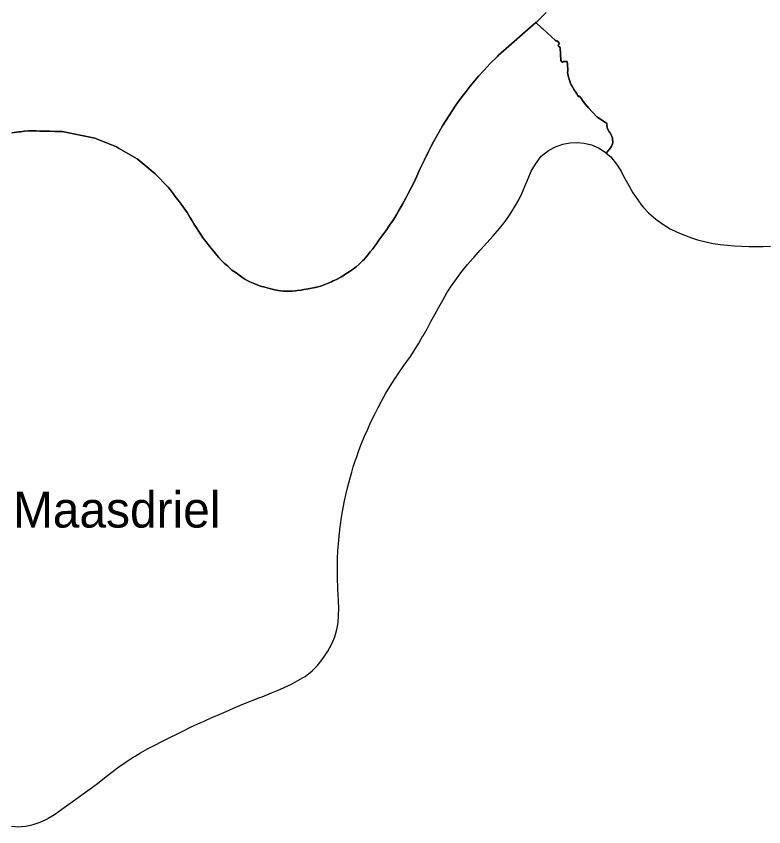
# Model space of a CAD drawing. Extents: x 113371 to 291721, y 393993 to 520143.
# Drawn here: x 148639 to 159083, y 416466 to 427782 of the extents above; entities that cross this region are included whole.
import ezdxf

# ---------------------------------------------------------------- set-up
doc = ezdxf.new("R2010")
doc.units = 0
doc.layers.add('Default', color=7, linetype='Continuous')
doc.layers.add('plaatsnamen', color=7, linetype='Continuous')

msp = doc.modelspace()

# ---------------------------------------------------------------- linework, layer by layer
at = {"layer": 'Default'}
for points in [[(153986.505625, 425071.1725), (154034.975625, 425158.1925), (154087.115625, 425250.9725), (154120.345625, 425313.7825), (154161.605625, 425394.4425), (154201.585625, 425476.5625), (154249.765625, 425580.5525), (154278.395625, 425644.2125), (154341.195625, 425778.3425), (154397.125625, 425894.2625), (154430.575625, 425960.3225), (154468.725625, 426028.9725), (154595.535625, 426249.2025), (154780.515625, 426538.5825), (154849.085625, 426638.0225), (154887.425625, 426683.3225), (154923.725625, 426732.1225), (154978.845625, 426803.2425), (155026.375625, 426861.5125), (155098.405625, 426944.2925), (155176.415625, 427030.0625), (155260.355625, 427121.3925), (155361.635625, 427221.1325), (155376.935625, 427238.0325), (155407.135625, 427265.8925), (155899.955625, 427692.0425), (155902.265625, 427694.0425), (155931.275625, 427722.2525), (156042.365625, 427833.5825)], [(156042.365625, 427833.5825), (155931.275625, 427722.2525), (155902.265625, 427694.0425), (155899.955625, 427692.0425), (155909.255625, 427683.7325), (155968.405625, 427628.1825), (155979.005625, 427618.3525), (155983.445625, 427615.4525), (155987.855625, 427611.0025), (155989.615625, 427609.2325), (156171.875625, 427441.2025), (156174.015625, 427439.5625), (156174.105625, 427439.5525), (156195.345625, 427435.7825)], [(156201.355625, 427434.5425), (156200.165625, 427434.7925), (156195.345625, 427435.7825), (156174.105625, 427439.5525), (156174.015625, 427439.5625), (156171.875625, 427441.2025), (155989.615625, 427609.2325), (155987.855625, 427611.0025), (155983.445625, 427615.4525), (155979.005625, 427618.3525), (155968.405625, 427628.1825), (155909.255625, 427683.7325), (155899.955625, 427692.0425), (155407.135625, 427265.8925), (155376.935625, 427238.0325), (155361.635625, 427221.1325), (155260.355625, 427121.3925), (155176.415625, 427030.0625), (155098.405625, 426944.2925), (155026.375625, 426861.5125), (154978.845625, 426803.2425), (154923.725625, 426732.1225), (154887.425625, 426683.3225), (154849.085625, 426638.0225), (154780.515625, 426538.5825), (154595.535625, 426249.2025), (154468.725625, 426028.9725), (154430.575625, 425960.3225), (154397.125625, 425894.2625), (154341.195625, 425778.3425), (154278.395625, 425644.2125), (154249.765625, 425580.5525), (154201.585625, 425476.5625), (154161.605625, 425394.4425), (154120.345625, 425313.7825), (154087.115625, 425250.9725), (154034.975625, 425158.1925), (153986.505625, 425071.1725)], [(156195.345625, 427435.7825), (156200.165625, 427434.7925), (156201.355625, 427434.5425), (156227.355625, 427400.2725), (156223.255625, 427395.3825), (156222.145625, 427393.2125), (156211.015625, 427377.6825), (156216.185625, 427365.5225), (156218.345625, 427363.6225), (156224.265625, 427357.8325), (156235.055625, 427345.2225), (156235.225625, 427345.0325), (156235.945625, 427344.1925), (156237.925625, 427341.0425), (156238.325625, 427340.4225), (156240.565625, 427336.8625), (156239.085625, 427329.9925), (156239.865625, 427309.1825), (156239.915625, 427307.6425), (156240.125625, 427301.9925), (156240.705625, 427287.4625), (156240.705625, 427287.3325), (156240.735625, 427286.8525), (156242.135625, 427259.3225), (156242.145625, 427259.1825), (156244.425625, 427214.5825), (156245.195625, 427199.6225), (156246.965625, 427165.0925), (156260.145625, 427143.7625), (156259.175625, 427141.0625), (156264.055625, 427141.4025), (156277.055625, 427142.3125), (156278.595625, 427142.4225), (156280.065625, 427142.5225), (156281.015625, 427146.8325), (156282.795625, 427147.9825), (156283.095625, 427148.1825), (156285.415625, 427148.2525)], [(156318.305625, 427150.8125), (156317.945625, 427149.3425), (156285.415625, 427148.2525), (156283.095625, 427148.1825), (156282.795625, 427147.9825), (156281.015625, 427146.8325), (156280.065625, 427142.5225), (156278.595625, 427142.4225), (156277.055625, 427142.3125), (156264.055625, 427141.4025), (156259.175625, 427141.0625), (156260.145625, 427143.7625), (156246.965625, 427165.0925), (156245.195625, 427199.6225), (156244.425625, 427214.5825), (156242.145625, 427259.1825), (156242.135625, 427259.3225), (156240.735625, 427286.8525), (156240.705625, 427287.3325), (156240.705625, 427287.4625), (156240.125625, 427301.9925), (156239.915625, 427307.6425), (156239.865625, 427309.1825), (156239.085625, 427329.9925), (156240.565625, 427336.8625), (156238.325625, 427340.4225), (156237.925625, 427341.0425), (156235.945625, 427344.1925), (156235.225625, 427345.0325), (156235.055625, 427345.2225), (156224.265625, 427357.8325), (156218.345625, 427363.6225), (156216.185625, 427365.5225), (156211.015625, 427377.6825), (156222.145625, 427393.2125), (156223.255625, 427395.3825), (156227.355625, 427400.2725), (156201.355625, 427434.5425)], [(156285.415625, 427148.2525), (156317.945625, 427149.3425), (156318.305625, 427150.8125), (156336.875625, 427151.6425), (156337.755625, 427134.0525), (156338.455625, 427120.0425), (156338.465625, 427119.8425), (156338.525625, 427118.4925), (156343.385625, 427018.6225), (156341.935625, 426994.3425), (156341.985625, 426993.3625), (156342.115625, 426990.5325), (156343.105625, 426983.7925), (156343.625625, 426980.2325), (156349.825625, 426950.9425), (156359.485625, 426919.0025), (156361.965625, 426908.6725), (156365.725625, 426892.7525), (156367.265625, 426888.2325), (156376.835625, 426861.0325), (156377.065625, 426860.3825), (156377.795625, 426858.3425), (156393.625625, 426822.7225), (156408.625625, 426797.8225), (156415.205625, 426786.7225), (156417.835625, 426782.2825), (156419.145625, 426780.0525), (156425.385625, 426769.4325), (156425.855625, 426768.6025), (156430.375625, 426760.7725), (156430.785625, 426760.0525), (156441.945625, 426742.2325), (156455.235625, 426721.2825), (156455.575625, 426720.7225), (156469.015625, 426699.3125), (156473.825625, 426691.5525), (156474.775625, 426690.0025), (156481.415625, 426679.6625)], [(156494.665625, 426660.7725), (156483.685625, 426676.1125), (156481.415625, 426679.6625), (156474.775625, 426690.0025), (156473.825625, 426691.5525), (156469.015625, 426699.3125), (156455.575625, 426720.7225), (156455.235625, 426721.2825), (156441.945625, 426742.2325), (156430.785625, 426760.0525), (156430.375625, 426760.7725), (156425.855625, 426768.6025), (156425.385625, 426769.4325), (156419.145625, 426780.0525), (156417.835625, 426782.2825), (156415.205625, 426786.7225), (156408.625625, 426797.8225), (156393.625625, 426822.7225), (156377.795625, 426858.3425), (156377.065625, 426860.3825), (156376.835625, 426861.0325), (156367.265625, 426888.2325), (156365.725625, 426892.7525), (156361.965625, 426908.6725), (156359.485625, 426919.0025), (156349.825625, 426950.9425), (156343.625625, 426980.2325), (156343.105625, 426983.7925), (156342.115625, 426990.5325), (156341.985625, 426993.3625), (156341.935625, 426994.3425), (156343.385625, 427018.6225), (156338.525625, 427118.4925), (156338.465625, 427119.8425), (156338.455625, 427120.0425), (156337.755625, 427134.0525), (156336.875625, 427151.6425), (156318.305625, 427150.8125)], [(156481.415625, 426679.6625), (156483.685625, 426676.1125), (156494.665625, 426660.7725), (156498.025625, 426662.7325), (156506.235625, 426667.5125), (156534.795625, 426629.1025), (156561.575625, 426593.1625), (156561.675625, 426593.0325), (156613.225625, 426523.4425), (156615.765625, 426524.8725), (156616.735625, 426523.8025), (156636.105625, 426502.4125), (156752.645625, 426378.5925), (156752.735625, 426378.5225), (156753.415625, 426378.0425), (156761.775625, 426373.8725), (156891.725625, 426285.9125), (156888.245625, 426277.0525), (156888.435625, 426272.2725), (156890.175625, 426257.5925), (156890.785625, 426250.3125), (156892.625625, 426235.5425), (156893.705625, 426230.4125), (156898.835625, 426217.3025), (156900.565625, 426212.0525), (156908.355625, 426192.9925), (156914.825625, 426180.1325), (156920.655625, 426171.3825), (156931.315625, 426157.1525), (156936.125625, 426149.4225), (156940.435625, 426143.2825), (156943.795625, 426137.9625), (156948.305625, 426129.1925), (156950.325625, 426125.1725), (156954.465625, 426115.7425), (156959.705625, 426102.4525), (156963.565625, 426092.9225), (156968.285625, 426077.2225)], [(156975.075625, 426021.4225), (156969.925625, 426066.0525), (156968.285625, 426077.2225), (156963.565625, 426092.9225), (156959.705625, 426102.4525), (156954.465625, 426115.7425), (156950.325625, 426125.1725), (156948.305625, 426129.1925), (156943.795625, 426137.9625), (156940.435625, 426143.2825), (156936.125625, 426149.4225), (156931.315625, 426157.1525), (156920.655625, 426171.3825), (156914.825625, 426180.1325), (156908.355625, 426192.9925), (156900.565625, 426212.0525), (156898.835625, 426217.3025), (156893.705625, 426230.4125), (156892.625625, 426235.5425), (156890.785625, 426250.3125), (156890.175625, 426257.5925), (156888.435625, 426272.2725), (156888.245625, 426277.0525), (156891.725625, 426285.9125), (156761.775625, 426373.8725), (156753.415625, 426378.0425), (156752.735625, 426378.5225), (156752.645625, 426378.5925), (156636.105625, 426502.4125), (156616.735625, 426523.8025), (156615.765625, 426524.8725), (156613.225625, 426523.4425), (156561.675625, 426593.0325), (156561.575625, 426593.1625), (156534.795625, 426629.1025), (156506.235625, 426667.5125), (156498.025625, 426662.7325), (156494.665625, 426660.7725)], [(148575.925625, 426153.8125), (148676.105625, 426166.0625), (148700.015625, 426168.9225), (148754.025625, 426175.3925), (148813.925625, 426182.4925), (148853.355625, 426181.3425), (148917.635625, 426179.9725), (148971.455625, 426178.8325), (149021.535625, 426177.5425), (149081.715625, 426176.1125), (149112.835625, 426175.2325), (149185.675625, 426173.4925), (149253.215625, 426171.9225), (149279.585625, 426171.4925), (149739.275625, 426079.8825), (150038.015625, 425958.2325), (150068.685625, 425940.6425), (150327.555625, 425792.1125), (150434.675625, 425702.7025), (150581.285625, 425580.5025), (150761.515625, 425396.2825), (150788.465625, 425361.9225), (150831.815625, 425306.2925), (150861.375625, 425266.7025), (150898.585625, 425220.4025), (150921.355625, 425188.2725), (150966.075625, 425126.1625), (151003.985625, 425073.4425), (151028.195625, 425039.9025), (151066.175625, 424975.8425), (151097.375625, 424923.7125), (151120.775625, 424884.9225), (151134.415625, 424862.0725)], [(148676.105625, 426166.0625), (148575.925625, 426153.8125)], [(151348.775625, 424559.5025), (151292.245625, 424632.0425), (151247.675625, 424689.2025), (151218.805625, 424733.3325), (151190.445625, 424776.6025), (151156.045625, 424828.3525), (151134.415625, 424862.0725), (151120.775625, 424884.9225), (151097.375625, 424923.7125), (151066.175625, 424975.8425), (151028.195625, 425039.9025), (151003.985625, 425073.4425), (150966.075625, 425126.1625), (150921.355625, 425188.2725), (150898.585625, 425220.4025), (150861.375625, 425266.7025), (150831.815625, 425306.2925), (150788.465625, 425361.9225), (150761.515625, 425396.2825), (150581.285625, 425580.5025), (150434.675625, 425702.7025), (150327.555625, 425792.1125), (150068.685625, 425940.6425), (150038.015625, 425958.2325), (149739.275625, 426079.8825), (149279.585625, 426171.4925), (149253.215625, 426171.9225), (149185.675625, 426173.4925), (149112.835625, 426175.2325), (149081.715625, 426176.1125), (149021.535625, 426177.5425), (148971.455625, 426178.8325), (148917.635625, 426179.9725), (148853.355625, 426181.3425), (148813.925625, 426182.4925), (148754.025625, 426175.3925), (148700.015625, 426168.9225), (148676.105625, 426166.0625)], [(156968.285625, 426077.2225), (156969.925625, 426066.0525), (156975.075625, 426021.4225), (156973.295625, 426012.8925), (156971.115625, 426002.4525), (156954.615625, 425966.7825), (156941.825625, 425942.0225), (156928.745625, 425926.5925), (156882.925625, 425871.2325), (156944.285625, 425817.7525), (157025.285625, 425717.7525), (157089.285625, 425617.7525), (157106.235625, 425586.3825), (157143.285625, 425517.7525), (157179.295625, 425451.0825), (157197.285625, 425417.7525), (157255.285625, 425317.7525), (157321.285625, 425217.7525), (157374.285625, 425143.7525), (157403.605625, 425112.0925), (157474.285625, 425035.7525), (157574.285625, 424948.7525), (157674.285625, 424876.7525), (157774.285625, 424815.7525), (157874.285625, 424767.7525), (157974.195625, 424724.9425), (158074.285625, 424685.7525), (158154.785625, 424659.9925), (158174.285625, 424653.7525), (158274.285625, 424629.7525), (158374.285625, 424610.7525), (158374.485625, 424610.7325), (158408.045625, 424606.0325), (158474.285625, 424596.7525), (158574.285625, 424583.7525), (158674.285625, 424575.7525), (158774.285625, 424569.7525), (158874.285625, 424566.7525)], [(154864.285625, 424217.7525), (154944.285625, 424317.7525), (155019.695625, 424400.6225), (155035.285625, 424417.7525), (155122.335625, 424517.7225), (155124.035625, 424519.6825), (155213.285625, 424617.7525), (155304.285625, 424717.7525), (155390.285625, 424817.7525), (155471.285625, 424917.7525), (155539.285625, 425017.7525), (155599.965625, 425114.0625), (155602.285625, 425117.7525), (155659.285625, 425217.7525), (155705.285625, 425317.7525), (155748.285625, 425417.7525), (155781.095625, 425492.3025), (155792.285625, 425517.7525), (155835.285625, 425617.7525), (155891.285625, 425717.7525), (155974.285625, 425826.7525), (156074.285625, 425906.7525), (156174.285625, 425959.7525), (156274.285625, 425996.7525), (156374.285625, 426015.7525), (156474.285625, 426019.7525), (156574.285625, 426010.7525), (156674.285625, 425985.7525), (156774.285625, 425944.7525), (156852.665625, 425893.0325), (156874.285625, 425878.7525), (156882.925625, 425871.2325), (156928.745625, 425926.5925), (156941.825625, 425942.0225), (156954.615625, 425966.7825), (156971.115625, 426002.4525), (156973.295625, 426012.8925), (156975.075625, 426021.4225)], [(153986.505625, 425071.1725), (153954.985625, 425018.4225), (153899.815625, 424924.7625), (153865.435625, 424876.3625), (153815.405625, 424803.1825), (153746.665625, 424709.1125), (153720.755625, 424673.5925), (153706.655625, 424653.2325), (153662.615625, 424592.2225), (153654.105625, 424581.0325), (153633.125625, 424551.2725), (153621.515625, 424536.0025), (153585.415625, 424490.7325), (153542.765625, 424438.5725), (153512.715625, 424403.4925), (153498.005625, 424387.3125), (153480.595625, 424369.4825), (153453.115625, 424343.3825), (153429.105625, 424321.2925), (153387.325625, 424284.2525), (153349.625625, 424255.6325), (153324.895625, 424237.6325), (153276.455625, 424203.7625), (153266.005625, 424196.9925), (153203.995625, 424156.7925), (153173.755625, 424138.8925), (153112.995625, 424107.3325), (153068.065625, 424085.4725), (153045.805625, 424075.3425), (153019.435625, 424064.0125), (152972.395625, 424044.4625), (152927.335625, 424026.6425), (152904.085625, 424018.4925), (152891.335625, 424014.5725), (152855.995625, 424004.9025), (152792.835625, 423990.2525), (152742.195625, 423980.3625), (152719.815625, 423976.2325)], [(152719.815625, 423976.2325), (152742.195625, 423980.3625), (152792.835625, 423990.2525), (152855.995625, 424004.9025), (152891.335625, 424014.5725), (152904.085625, 424018.4925), (152927.335625, 424026.6425), (152972.395625, 424044.4625), (153019.435625, 424064.0125), (153045.805625, 424075.3425), (153068.065625, 424085.4725), (153112.995625, 424107.3325), (153173.755625, 424138.8925), (153203.995625, 424156.7925), (153266.005625, 424196.9925), (153276.455625, 424203.7625), (153324.895625, 424237.6325), (153349.625625, 424255.6325), (153387.325625, 424284.2525), (153429.105625, 424321.2925), (153453.115625, 424343.3825), (153480.595625, 424369.4825), (153498.005625, 424387.3125), (153512.715625, 424403.4925), (153542.765625, 424438.5725), (153585.415625, 424490.7325), (153621.515625, 424536.0025), (153633.125625, 424551.2725), (153654.105625, 424581.0325), (153662.615625, 424592.2225), (153706.655625, 424653.2325), (153720.755625, 424673.5925), (153746.665625, 424709.1125), (153815.405625, 424803.1825), (153865.435625, 424876.3625), (153899.815625, 424924.7625), (153954.985625, 425018.4225), (153986.505625, 425071.1725)], [(151134.415625, 424862.0725), (151156.045625, 424828.3525), (151190.445625, 424776.6025), (151218.805625, 424733.3325), (151247.675625, 424689.2025), (151292.245625, 424632.0425), (151348.775625, 424559.5025), (151348.955625, 424559.2925), (151357.975625, 424547.7125), (151380.285625, 424519.6525), (151466.485625, 424419.1525), (151511.135625, 424367.1025), (151546.265625, 424335.0325), (151589.815625, 424294.8725), (151652.085625, 424236.9525), (151713.725625, 424197.1925), (151769.385625, 424158.3325), (151804.495625, 424129.8825), (151832.035625, 424112.0925), (151872.945625, 424089.4925), (151902.545625, 424074.4625), (151925.715625, 424063.3825), (151948.565625, 424053.2125), (151972.355625, 424043.7225), (152006.455625, 424030.9325), (152038.375625, 424019.8025), (152053.355625, 424015.2525), (152112.955625, 423997.4025), (152144.235625, 423989.0025), (152176.835625, 423980.8325), (152252.035625, 423963.6825), (152254.015625, 423961.5225), (152300.095625, 423954.4825), (152331.645625, 423949.2625), (152366.655625, 423945.3925), (152379.665625, 423944.5125), (152436.585625, 423943.7225), (152496.305625, 423945.1425)], [(152719.815625, 423976.2325), (152689.965625, 423970.7325), (152658.675625, 423965.9825), (152618.345625, 423958.9225), (152563.625625, 423950.6325), (152541.915625, 423948.1325), (152496.305625, 423945.1425), (152436.585625, 423943.7225), (152379.665625, 423944.5125), (152366.655625, 423945.3925), (152331.645625, 423949.2625), (152300.095625, 423954.4825), (152254.015625, 423961.5225), (152252.035625, 423963.6825), (152176.835625, 423980.8325), (152144.235625, 423989.0025), (152112.955625, 423997.4025), (152053.355625, 424015.2525), (152038.375625, 424019.8025), (152006.455625, 424030.9325), (151972.355625, 424043.7225), (151948.565625, 424053.2125), (151925.715625, 424063.3825), (151902.545625, 424074.4625), (151872.945625, 424089.4925), (151832.035625, 424112.0925), (151804.495625, 424129.8825), (151769.385625, 424158.3325), (151713.725625, 424197.1925), (151652.085625, 424236.9525), (151589.815625, 424294.8725), (151546.265625, 424335.0325), (151511.135625, 424367.1025), (151466.485625, 424419.1525), (151380.285625, 424519.6525), (151357.975625, 424547.7125), (151348.955625, 424559.2925), (151348.775625, 424559.5025)], [(158874.285625, 424566.7525), (158973.985625, 424564.7625), (158974.285625, 424564.7525), (159074.285625, 424567.7525), (159174.285625, 424571.7525)], [(153272.285625, 421217.7525), (153300.285625, 421317.7525), (153327.285625, 421417.7525), (153348.625625, 421488.8825), (153357.285625, 421517.7525), (153390.055625, 421614.1225), (153391.285625, 421617.7525), (153427.285625, 421717.7525), (153464.285625, 421817.7525), (153505.285625, 421917.7525), (153549.285625, 422017.7525), (153593.285625, 422117.7525), (153643.285625, 422217.7525), (153694.285625, 422317.7525), (153737.035625, 422399.9725), (153746.285625, 422417.7525), (153804.285625, 422517.7525), (153863.285625, 422617.7525), (153926.285625, 422717.7525), (153951.195625, 422753.9525), (153955.185625, 422759.7525), (153995.285625, 422817.7525), (154026.845625, 422862.8425), (154065.285625, 422917.7525), (154136.285625, 423017.7525), (154202.285625, 423117.7525), (154262.285625, 423217.7525), (154321.285625, 423317.7525), (154322.585625, 423320.0325), (154378.285625, 423417.7525), (154432.285625, 423517.7525), (154489.285625, 423617.7525), (154544.285625, 423717.7525), (154597.285625, 423817.7525), (154655.285625, 423917.7525), (154718.285625, 424017.7525), (154788.285625, 424117.7525), (154864.285625, 424217.7525)], [(152496.305625, 423945.1425), (152541.915625, 423948.1325), (152563.625625, 423950.6325), (152618.345625, 423958.9225), (152658.675625, 423965.9825), (152689.965625, 423970.7325), (152719.815625, 423976.2325)], [(152444.915625, 418439.9525), (152474.285625, 418453.7525), (152574.285625, 418505.7525), (152648.285625, 418549.4125), (152674.285625, 418564.7525), (152774.285625, 418641.7525), (152833.675625, 418701.9325), (152849.285625, 418717.7525), (152928.285625, 418817.7525), (152993.285625, 418917.7525), (153047.285625, 419017.7525), (153091.285625, 419117.7525), (153118.285625, 419217.7525), (153126.665625, 419267.0025), (153135.285625, 419317.7525), (153142.285625, 419417.7525), (153144.285625, 419517.7525), (153140.285625, 419617.7525), (153135.285625, 419717.7525), (153133.035625, 419774.2325), (153132.295625, 419792.6825), (153131.285625, 419817.7525), (153127.285625, 419917.7525), (153126.285625, 420017.7525), (153127.285625, 420117.7525), (153129.285625, 420217.7525), (153133.285625, 420317.7525), (153139.285625, 420417.7525), (153149.285625, 420517.7525), (153152.335625, 420543.1025), (153154.085625, 420557.7225), (153161.285625, 420617.7525), (153173.285625, 420717.7525), (153188.285625, 420817.7525), (153206.285625, 420917.7525), (153226.285625, 421017.7525), (153248.285625, 421117.7525), (153272.285625, 421217.7525)], [(149574.285625, 416924.7525), (149674.285625, 416997.7525), (149674.385625, 416997.8225), (149774.285625, 417071.7525), (149874.285625, 417149.7525), (149974.285625, 417226.7525), (150074.285625, 417302.7525), (150174.285625, 417372.7525), (150274.285625, 417436.7525), (150299.055625, 417451.6225), (150374.285625, 417496.7525), (150474.285625, 417554.7525), (150574.285625, 417605.7525), (150674.285625, 417655.7525), (150776.395625, 417706.9825), (150811.325625, 417724.8025), (150864.075625, 417750.5125), (150874.285625, 417754.7525), (150974.285625, 417804.7525), (151074.285625, 417854.7525), (151174.285625, 417901.7525), (151231.625625, 417926.9825), (151274.285625, 417945.7525), (151374.285625, 417989.7525), (151474.285625, 418032.7525), (151574.285625, 418075.7525), (151674.285625, 418120.7525), (151738.705625, 418149.1025), (151774.285625, 418164.7525), (151874.285625, 418204.7525), (151974.285625, 418243.7525), (152039.315625, 418268.4725), (152074.285625, 418281.7525), (152174.285625, 418320.7525), (152205.845625, 418334.0125), (152274.285625, 418362.7525), (152374.285625, 418406.7525), (152444.915625, 418439.9525)], [(148574.285625, 416474.7525), (148674.285625, 416465.7525), (148708.615625, 416469.1925), (148774.285625, 416475.7525), (148874.285625, 416497.7525), (148974.285625, 416528.7525), (149074.285625, 416575.7525), (149087.185625, 416583.8825), (149174.285625, 416638.7525), (149274.285625, 416710.7525), (149374.285625, 416781.7525), (149405.515625, 416803.9325), (149474.285625, 416852.7525), (149574.285625, 416924.7525)]]:
    msp.add_lwpolyline(points, dxfattribs=at)

# ---------------------------------------------------------------- texts
at = {"layer": 'plaatsnamen'}
msp.add_text('Maasdriel', height=500, dxfattribs=at).set_placement((148593.745214, 420643.307571))

doc.saveas('drawing.dxf')
